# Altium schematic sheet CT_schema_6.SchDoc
size 254 x 194 mm
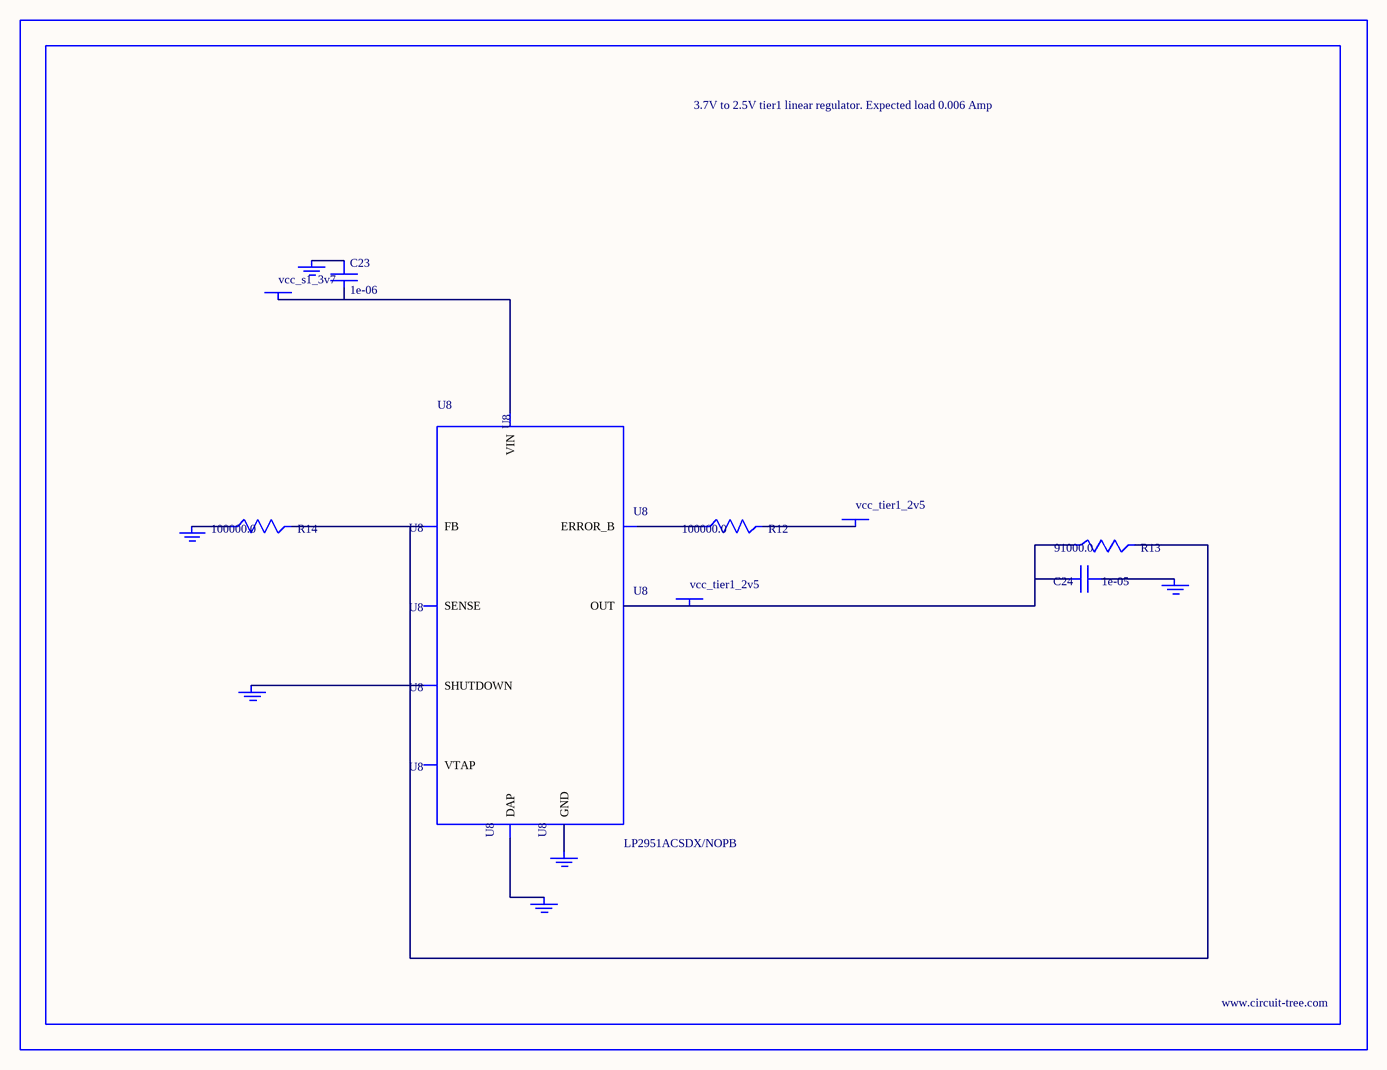
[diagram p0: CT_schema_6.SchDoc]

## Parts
BORDER5  (no value)
C23  1e-06  [C0603]
C24  1e-05  [C1210]
GND_INSTANCE_5_0  (no value)
GND_INSTANCE_5_1  (no value)
GND_INSTANCE_5_2  (no value)
GND_INSTANCE_5_3  (no value)
GND_INSTANCE_5_4  (no value)
GND_INSTANCE_5_5  (no value)
POWER_INSTANCE_5_0  vcc_tier1_2v5
POWER_INSTANCE_5_1  vcc_s1_3v7
POWER_INSTANCE_5_2  vcc_tier1_2v5
R12  100000.0  [R0603]
R13  91000.0  [R0603]
R14  100000.0  [R0603]
U8  LP2951ACSDX/NOPB  [WSON-8]

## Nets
NetC23_1: C23.1 GND_INSTANCE_5_3.0(GND)
NetC23_2: C23.2 POWER_INSTANCE_5_1.0(PWR) U8.8(VIN)
NetC24_1: C24.1 GND_INSTANCE_5_0.0(GND)
NetC24_2: C24.2 POWER_INSTANCE_5_2.0(PWR) R13.1 U8.1(OUT)
NetGND_INSTANCE_5_1_0: GND_INSTANCE_5_1.0(GND) U8.3(SHUTDOWN)
NetGND_INSTANCE_5_2_0: GND_INSTANCE_5_2.0(GND) R14.1
NetGND_INSTANCE_5_4_0: GND_INSTANCE_5_4.0(GND) U8.PAD(DAP)
NetGND_INSTANCE_5_5_0: GND_INSTANCE_5_5.0(GND) U8.4(GND)
NetPOWER_INSTANCE_5_0_0: POWER_INSTANCE_5_0.0(PWR) R12.2
NetR12_1: R12.1 U8.5(ERROR_B)
NetR13_2: R13.2 R14.2 U8.7(FB)

Not connected (* = marked no-connect by the designer): U8 2(SENSE) 6(VTAP)

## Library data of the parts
BORDER5 = BORDER_PAGE5
C23 = C0603C105K3RACTU
C24 = GRM32DR61E106MA12L
GND_INSTANCE_5_0-GND_INSTANCE_5_5 = GND
POWER_INSTANCE_5_0-POWER_INSTANCE_5_2 = PWR
R12 R14 = RC0603JR-07100KL
R13 = RC0603JR-0791KL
